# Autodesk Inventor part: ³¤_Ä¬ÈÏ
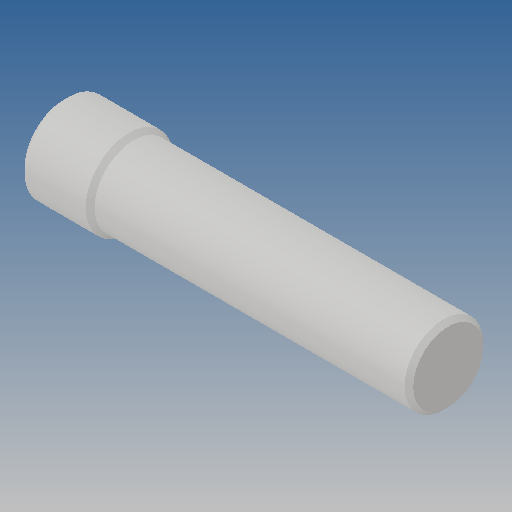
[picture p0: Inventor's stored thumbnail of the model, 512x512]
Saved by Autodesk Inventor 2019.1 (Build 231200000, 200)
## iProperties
Created: 2012-10
Part Number: ³¤_Ä¬ÈÏ
Material: Ogólny
Document SubType Name: Modeling
Designer: CADENGINEERING4
Density: 1 g/cm^3
Appearance: Domyślna
Author: CADENGINEERING4
Revision Number: ÈÎºÎ
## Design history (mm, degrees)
feature "NONE"
node "Bryła1"
